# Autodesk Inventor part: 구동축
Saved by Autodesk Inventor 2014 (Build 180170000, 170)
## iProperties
Created: 2026-01
Part Number: 구동축
Material: 일반
Document SubType Name: Modeling
Designer: dg
Density: 1 g/cm^3
Appearance: 기본값
Author: dg
Author: jhkim
Creation Date: 2026-01-09
Sending System: Autodesk Inventor 2026
Preprocessor: ST-DEVELOPER v20.1
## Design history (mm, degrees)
node "구동축1"
node "솔리드1"
node "기준1"
